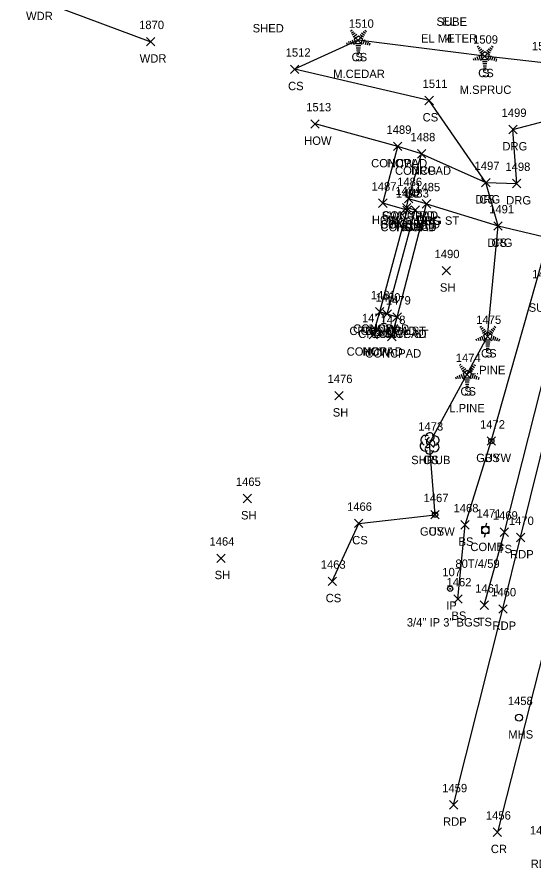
# Model space of a CAD drawing. Extents: x 1477930 to 1480780, y 774090 to 784647.
# Drawn here: x 1479170.3 to 1479293.7, y 774132.1 to 774335.2 of the extents above; entities that cross this region are included whole.
import ezdxf

# ---------------------------------------------------------------- set-up
doc = ezdxf.new("R2010")
doc.units = 0
for name, color, linetype in [('L_A', 7, 'Continuous'), ('L_C', 7, 'Continuous'), ('L_I', 7, 'Continuous'), ('L_TIC', 7, 'Continuous'), ('LAWA', 7, 'Continuous'), ('LBC', 7, 'Continuous'), ('LELB', 7, 'Continuous'), ('LS', 7, 'Continuous'), ('LSH', 7, 'Continuous'), ('LTC', 7, 'Continuous'), ('M_A', 7, 'Continuous'), ('M_C', 7, 'Continuous'), ('M_I', 7, 'Continuous'), ('MPIR', 7, 'Continuous'), ('P_A', 7, 'Continuous'), ('P_I', 7, 'Continuous'), ('P_TIC', 7, 'Continuous'), ('PET', 7, 'Continuous'), ('PRC', 7, 'Continuous'), ('R_A', 7, 'Continuous'), ('R_I', 7, 'Continuous'), ('R_TIC', 7, 'Continuous'), ('RDG', 7, 'Continuous'), ('RSW', 7, 'Continuous'), ('U_A', 7, 'Continuous'), ('U_C', 7, 'Continuous'), ('U_I', 7, 'Continuous'), ('UP', 7, 'Continuous'), ('UPGW', 7, 'Continuous'), ('USMH', 7, 'Continuous')]:
    doc.layers.add(name, color=color, linetype=linetype)

msp = doc.modelspace()

# ---------------------------------------------------------------- linework, layer by layer
at = {"layer": 'L_TIC'}
for points in [[(1479201.22, 774328.33), (1479203.22, 774330.33)], [(1479203.22, 774328.33), (1479201.22, 774330.33)], [(1479250.69, 774328.65), (1479252.69, 774330.65)], [(1479252.69, 774328.65), (1479250.69, 774330.65)], [(1479280.89, 774324.86), (1479282.89, 774326.86)], [(1479282.89, 774324.86), (1479280.89, 774326.86)], [(1479235.54, 774321.75), (1479237.54, 774323.75)], [(1479237.54, 774321.75), (1479235.54, 774323.75)], [(1479235.54, 774321.75), (1479237.54, 774323.75)], [(1479237.54, 774321.75), (1479235.54, 774323.75)], [(1479267.64, 774314.29), (1479269.64, 774316.29)], [(1479269.64, 774314.29), (1479267.64, 774316.29)], [(1479240.43, 774308.7), (1479242.43, 774310.7)], [(1479242.43, 774308.7), (1479240.43, 774310.7)], [(1479260.16, 774303.33), (1479262.16, 774305.33)], [(1479262.16, 774303.33), (1479260.16, 774305.33)], [(1479260.16, 774303.33), (1479262.16, 774305.33)], [(1479262.16, 774303.33), (1479260.16, 774305.33)], [(1479265.85, 774301.56), (1479267.85, 774303.56)], [(1479267.85, 774301.56), (1479265.85, 774303.56)], [(1479281.17, 774294.71), (1479283.17, 774296.71)], [(1479283.17, 774294.71), (1479281.17, 774296.71)], [(1479256.59, 774289.79), (1479258.59, 774291.79)], [(1479258.59, 774289.79), (1479256.59, 774291.79)], [(1479262.75, 774290.86), (1479264.75, 774292.86)], [(1479264.75, 774290.86), (1479262.75, 774292.86)], [(1479262.26, 774288.74), (1479264.26, 774290.74)], [(1479264.26, 774288.74), (1479262.26, 774290.74)], [(1479262.38, 774288.09), (1479264.38, 774290.09)], [(1479264.38, 774288.09), (1479262.38, 774290.09)], [(1479262.38, 774288.09), (1479264.38, 774290.09)], [(1479264.38, 774288.09), (1479262.38, 774290.09)], [(1479284.08, 774284.35), (1479286.08, 774286.35)], [(1479286.08, 774284.35), (1479284.08, 774286.35)], [(1479271.72, 774273.67), (1479273.72, 774275.67)], [(1479273.72, 774273.67), (1479271.72, 774275.67)], [(1479255.85, 774263.86), (1479257.85, 774265.86)], [(1479257.85, 774263.86), (1479255.85, 774265.86)], [(1479255.85, 774263.86), (1479257.85, 774265.86)], [(1479257.85, 774263.86), (1479255.85, 774265.86)], [(1479257.62, 774263.31), (1479259.62, 774265.31)], [(1479259.62, 774263.31), (1479257.62, 774265.31)], [(1479260.01, 774262.6), (1479262.01, 774264.6)], [(1479262.01, 774262.6), (1479260.01, 774264.6)], [(1479254.31, 774258.39), (1479256.31, 774260.39)], [(1479256.31, 774258.39), (1479254.31, 774260.39)], [(1479254.31, 774258.39), (1479256.31, 774260.39)], [(1479256.31, 774258.39), (1479254.31, 774260.39)], [(1479258.74, 774257.95), (1479260.74, 774259.95)], [(1479260.74, 774257.95), (1479258.74, 774259.95)], [(1479281.57, 774257.97), (1479283.57, 774259.97)], [(1479283.57, 774257.97), (1479281.57, 774259.97)], [(1479276.67, 774248.87), (1479278.67, 774250.87)], [(1479278.67, 774248.87), (1479276.67, 774250.87)], [(1479246.15, 774243.86), (1479248.15, 774245.86)], [(1479248.15, 774243.86), (1479246.15, 774245.86)], [(1479267.73, 774232.51), (1479269.73, 774234.51)], [(1479269.73, 774232.51), (1479267.73, 774234.51)], [(1479282.47, 774233), (1479284.47, 774235)], [(1479284.47, 774233), (1479282.47, 774235)], [(1479224.26, 774219.31), (1479226.26, 774221.31)], [(1479226.26, 774219.31), (1479224.26, 774221.31)], [(1479269.05, 774215.44), (1479271.05, 774217.44)], [(1479271.05, 774215.44), (1479269.05, 774217.44)], [(1479250.84, 774213.37), (1479252.84, 774215.37)], [(1479252.84, 774213.37), (1479250.84, 774215.37)], [(1479276.2, 774213.02), (1479278.2, 774215.02)], [(1479278.2, 774213.02), (1479276.2, 774215.02)], [(1479276.2, 774213.02), (1479278.2, 774215.02)], [(1479278.2, 774213.02), (1479276.2, 774215.02)], [(1479285.59, 774211.27), (1479287.59, 774213.27)], [(1479287.59, 774211.27), (1479285.59, 774213.27)], [(1479285.59, 774211.27), (1479287.59, 774213.27)], [(1479287.59, 774211.27), (1479285.59, 774213.27)], [(1479217.97, 774205.06), (1479219.97, 774207.06)], [(1479219.97, 774205.06), (1479217.97, 774207.06)], [(1479244.52, 774199.55), (1479246.52, 774201.55)], [(1479246.52, 774199.55), (1479244.52, 774201.55)], [(1479274.52, 774195.34), (1479276.52, 774197.34)], [(1479276.52, 774195.34), (1479274.52, 774197.34)], [(1479280.8, 774193.85), (1479282.8, 774195.85)], [(1479282.8, 774193.85), (1479280.8, 774195.85)]]:
    msp.add_lwpolyline(points, dxfattribs=at)
at = {"layer": 'LAWA'}
msp.add_lwpolyline([(1479132.45, 774321.38), (1479148.05, 774348), (1479175.1, 774339.47), (1479202.22, 774329.33)], dxfattribs=at)
at = {"layer": 'LBC'}
msp.add_lwpolyline([(1479255.31, 774259.39), (1479256.85, 774264.86), (1479263.38, 774289.09), (1479257.59, 774290.79), (1479261.16, 774304.33), (1479241.43, 774309.7)], dxfattribs=at)
at = {"layer": 'LELB'}
for points in [[(1479286.59, 774212.27), (1479303.75, 774279.72), (1479306.97, 774294.46), (1479314.06, 774320.63), (1479317.48, 774329.95), (1479319.72, 774342.37), (1479300.83, 774349.59), (1479294.56, 774350.02), (1479293.95, 774358.81)], [(1479314.06, 774320.63), (1479295.94, 774324.28), (1479281.89, 774325.86), (1479251.69, 774329.65), (1479236.54, 774322.75)], [(1479245.52, 774200.55), (1479251.84, 774214.37), (1479270.05, 774216.44), (1479268.73, 774233.51), (1479277.67, 774249.87), (1479282.57, 774258.97), (1479285.08, 774285.35), (1479282.17, 774295.71), (1479268.64, 774315.29), (1479236.54, 774322.75)], [(1479277.2, 774214.02), (1479283.47, 774234), (1479297.19, 774282.52), (1479300.07, 774295.97), (1479304.88, 774316.5), (1479296.39, 774315.47)], [(1479275.52, 774196.34), (1479277.2, 774214.02)], [(1479281.8, 774194.85), (1479286.59, 774212.27)]]:
    msp.add_lwpolyline(points, dxfattribs=at)
at = {"layer": 'LS'}
for points in [[(1479263.38, 774289.09), (1479263.26, 774289.74), (1479263.75, 774291.86), (1479266.85, 774302.56), (1479261.16, 774304.33)], [(1479255.31, 774259.39), (1479259.74, 774258.95), (1479261.01, 774263.6), (1479258.62, 774264.31), (1479256.85, 774264.86)]]:
    msp.add_lwpolyline(points, dxfattribs=at)
at = {"layer": 'LSH'}
msp.add_line((1479268.73, 774233.51), (1479268.73, 774233.51), dxfattribs=at)
msp.add_line((1479268.73, 774233.51), (1479268.73, 774233.51), dxfattribs=at)
msp.add_arc((1479268.78, 774234.95), 1.05, 335.5272, 180.9563, dxfattribs=at)
for centre, major_axis, ratio, start_param, end_param in [((1479267.94, 774234.18), (1.21, -0.51), 0.895232, 1.570796, 4.712389), ((1479268.53, 774233.97), (-0.208, -0.792), 0.645439, 3.141593, 6.283185), ((1479269.23, 774233.35), (-0.5, 0.667), 0.989748, 3.141593, 6.283185), ((1479269.78, 774234.1), (-1.14, -0.48), 0.949671, 1.570796, 4.712389), ((1479267.65, 774232.8), (0.58, -1.04), 0.959034, 3.141593, 6.283185), ((1479268.73, 774232.01), (0.26, 1.06), 0.942809, 1.570796, 4.712389), ((1479268.28, 774232.76), (-0.625, -0.083), 0.423636, 0, 3.141593), ((1479269.73, 774232.68), (-1.09, 0.79), 0.841452, 1.570796, 4.712389)]:
    msp.add_ellipse(centre, major_axis=major_axis, ratio=ratio, start_param=start_param, end_param=end_param, dxfattribs=at)
at = {"layer": 'LTC'}
for p, q in [((1479249.88, 774331.86), (1479250.24, 774332.12)), ((1479250.09, 774331.39), (1479250.62, 774331.78)), ((1479252.91, 774331.75), (1479253.46, 774331.35)), ((1479253.28, 774332.1), (1479253.7, 774331.79)), ((1479249.83, 774329.57), (1479250.1, 774328.73)), ((1479250.28, 774329.79), (1479250.61, 774328.77)), ((1479250.3, 774330.93), (1479251.01, 774331.44)), ((1479250.51, 774330.46), (1479251.39, 774331.1)), ((1479250.74, 774330.01), (1479251.75, 774330.74)), ((1479250.74, 774330.01), (1479251.12, 774328.81)), ((1479251.75, 774330.74), (1479252.75, 774330.02)), ((1479252.17, 774331.05), (1479252.98, 774330.46)), ((1479252.75, 774330.02), (1479252.35, 774328.81)), ((1479252.54, 774331.4), (1479253.22, 774330.91)), ((1479253.18, 774329.74), (1479252.85, 774328.7)), ((1479253.63, 774329.49), (1479253.34, 774328.61)), ((1479248.92, 774329.14), (1479249.07, 774328.67)), ((1479249.37, 774329.35), (1479249.58, 774328.7)), ((1479252.35, 774328.81), (1479251.12, 774328.81)), ((1479252.32, 774328.31), (1479251.17, 774328.31)), ((1479252.23, 774327.81), (1479251.24, 774327.81)), ((1479254.07, 774329.24), (1479253.84, 774328.51)), ((1479254.52, 774328.99), (1479254.33, 774328.42)), ((1479280.09, 774328.07), (1479280.44, 774328.33)), ((1479280.3, 774327.6), (1479280.83, 774327.99)), ((1479280.51, 774327.14), (1479281.21, 774327.65)), ((1479282.75, 774327.61), (1479283.43, 774327.12)), ((1479283.12, 774327.96), (1479283.67, 774327.56)), ((1479283.49, 774328.31), (1479283.91, 774328.01)), ((1479252.15, 774327.31), (1479251.32, 774327.31)), ((1479252.07, 774326.81), (1479251.39, 774326.81)), ((1479279.58, 774325.57), (1479279.79, 774324.91)), ((1479280.03, 774325.78), (1479280.3, 774324.95)), ((1479280.49, 774326), (1479280.82, 774324.98)), ((1479280.72, 774326.67), (1479281.6, 774327.31)), ((1479280.94, 774326.22), (1479281.96, 774326.95)), ((1479280.94, 774326.22), (1479281.33, 774325.02)), ((1479281.96, 774326.95), (1479282.95, 774326.23)), ((1479282.38, 774327.27), (1479283.18, 774326.68)), ((1479282.95, 774326.23), (1479282.56, 774325.02)), ((1479283.39, 774325.96), (1479283.05, 774324.92)), ((1479283.83, 774325.71), (1479283.55, 774324.82)), ((1479284.28, 774325.46), (1479284.04, 774324.73)), ((1479279.12, 774325.35), (1479279.27, 774324.88)), ((1479282.56, 774325.02), (1479281.33, 774325.02)), ((1479282.52, 774324.52), (1479281.38, 774324.52)), ((1479282.44, 774324.02), (1479281.45, 774324.02)), ((1479282.36, 774323.52), (1479281.52, 774323.52)), ((1479284.72, 774325.21), (1479284.54, 774324.63)), ((1479282.27, 774323.02), (1479281.6, 774323.02)), ((1479280.77, 774261.17), (1479281.12, 774261.43)), ((1479280.98, 774260.71), (1479281.51, 774261.09)), ((1479281.19, 774260.24), (1479281.89, 774260.75)), ((1479283.43, 774260.72), (1479284.1, 774260.22)), ((1479283.8, 774261.07), (1479284.35, 774260.67)), ((1479284.17, 774261.41), (1479284.59, 774261.11)), ((1479279.8, 774258.45), (1479279.95, 774257.99)), ((1479280.26, 774258.67), (1479280.47, 774258.02)), ((1479280.71, 774258.89), (1479280.98, 774258.05)), ((1479281.17, 774259.1), (1479281.5, 774258.08)), ((1479281.4, 774259.78), (1479282.28, 774260.42)), ((1479281.62, 774259.32), (1479282.63, 774260.06)), ((1479281.62, 774259.32), (1479282.01, 774258.13)), ((1479282.63, 774260.06), (1479283.63, 774259.33)), ((1479283.05, 774260.37), (1479283.86, 774259.78)), ((1479283.63, 774259.33), (1479283.24, 774258.13)), ((1479284.07, 774259.06), (1479283.73, 774258.02)), ((1479284.51, 774258.81), (1479284.23, 774257.93)), ((1479284.96, 774258.56), (1479284.72, 774257.83)), ((1479283.24, 774258.13), (1479282.01, 774258.13)), ((1479283.2, 774257.63), (1479282.06, 774257.63)), ((1479283.12, 774257.13), (1479282.13, 774257.13)), ((1479283.03, 774256.63), (1479282.2, 774256.63)), ((1479285.4, 774258.31), (1479285.22, 774257.74)), ((1479282.95, 774256.13), (1479282.28, 774256.13)), ((1479275.86, 774252.08), (1479276.22, 774252.34)), ((1479279.26, 774252.32), (1479279.68, 774252.02)), ((1479276.07, 774251.62), (1479276.6, 774252)), ((1479276.28, 774251.15), (1479276.99, 774251.66)), ((1479276.49, 774250.68), (1479277.37, 774251.32)), ((1479276.72, 774250.23), (1479277.73, 774250.96)), ((1479277.73, 774250.96), (1479278.73, 774250.24)), ((1479278.15, 774251.28), (1479278.96, 774250.69)), ((1479278.52, 774251.63), (1479279.2, 774251.13)), ((1479278.89, 774251.97), (1479279.44, 774251.57)), ((1479274.9, 774249.36), (1479275.05, 774248.89)), ((1479275.35, 774249.58), (1479275.56, 774248.93)), ((1479275.81, 774249.79), (1479276.08, 774248.96)), ((1479276.26, 774250.01), (1479276.59, 774248.99)), ((1479276.72, 774250.23), (1479277.1, 774249.04)), ((1479278.33, 774249.04), (1479277.1, 774249.04)), ((1479278.3, 774248.54), (1479277.15, 774248.54)), ((1479278.73, 774250.24), (1479278.33, 774249.04)), ((1479279.16, 774249.97), (1479278.82, 774248.93)), ((1479279.61, 774249.72), (1479279.32, 774248.83)), ((1479280.05, 774249.47), (1479279.81, 774248.74)), ((1479280.5, 774249.22), (1479280.31, 774248.64)), ((1479278.21, 774248.04), (1479277.22, 774248.04)), ((1479278.13, 774247.54), (1479277.3, 774247.54)), ((1479278.04, 774247.04), (1479277.37, 774247.04))]:
    msp.add_line(p, q, dxfattribs=at)
at = {"layer": 'MPIR'}
for radius in [0.625, 0.0833]:
    msp.add_circle((1479273.66, 774198.76), radius, dxfattribs=at)
at = {"layer": 'P_TIC'}
for points in [[(1479289.45, 774210), (1479291.45, 774212)], [(1479291.45, 774210), (1479289.45, 774212)], [(1479289.45, 774210), (1479291.45, 774212)], [(1479291.45, 774210), (1479289.45, 774212)], [(1479285.26, 774192.96), (1479287.26, 774194.96)], [(1479287.26, 774192.96), (1479285.26, 774194.96)], [(1479273.46, 774146.2), (1479275.46, 774148.2)], [(1479275.46, 774146.2), (1479273.46, 774148.2)], [(1479283.93, 774139.68), (1479285.93, 774141.68)], [(1479285.93, 774139.68), (1479283.93, 774141.68)]]:
    msp.add_lwpolyline(points, dxfattribs=at)
at = {"layer": 'PET'}
for points in [[(1479290.45, 774211), (1479306.91, 774277.39), (1479311.78, 774295.77), (1479318.73, 774320.25), (1479320.95, 774328.78), (1479324.18, 774341.9), (1479331.38, 774365.72), (1479345.79, 774423.22), (1479362.09, 774490.12), (1479368.03, 774516.32), (1479374.9, 774550.83), (1479383.52, 774593.51), (1479391.98, 774640.39), (1479380.39, 774660.29), (1479367.57, 774658.29), (1479344.84, 774648.04), (1479309.03, 774631.85), (1479275.88, 774616.72), (1479247.66, 774604.4), (1479226.65, 774595.78), (1479182.4, 774576.78), (1479137.48, 774556.65)], [(1479274.46, 774147.2), (1479286.26, 774193.96), (1479290.45, 774211)]]:
    msp.add_lwpolyline(points, dxfattribs=at)
at = {"layer": 'PRC'}
msp.add_lwpolyline([(1479418.32, 774694.97), (1479413.6, 774667.54), (1479403.41, 774616.88), (1479393.18, 774569.31), (1479382.15, 774520.62), (1479370.95, 774473.44), (1479362, 774437.8), (1479350.26, 774392.93), (1479347.88, 774382.5), (1479334.29, 774330.6), (1479333.84, 774328.63), (1479325.02, 774295.54), (1479313.51, 774250.57), (1479296.99, 774187.82), (1479284.93, 774140.68)], dxfattribs=at)
at = {"layer": 'R_TIC'}
for points in [[(1479287.63, 774307.37), (1479289.63, 774309.37)], [(1479289.63, 774307.37), (1479287.63, 774309.37)], [(1479265.85, 774301.56), (1479267.85, 774303.56)], [(1479267.85, 774301.56), (1479265.85, 774303.56)], [(1479281.17, 774294.71), (1479283.17, 774296.71)], [(1479283.17, 774294.71), (1479281.17, 774296.71)], [(1479288.53, 774294.48), (1479290.53, 774296.48)], [(1479290.53, 774294.48), (1479288.53, 774296.48)], [(1479262.75, 774290.86), (1479264.75, 774292.86)], [(1479264.75, 774290.86), (1479262.75, 774292.86)], [(1479267.01, 774289.63), (1479269.01, 774291.63)], [(1479269.01, 774289.63), (1479267.01, 774291.63)], [(1479267.01, 774289.63), (1479269.01, 774291.63)], [(1479269.01, 774289.63), (1479267.01, 774291.63)], [(1479262.26, 774288.74), (1479264.26, 774290.74)], [(1479264.26, 774288.74), (1479262.26, 774290.74)], [(1479264.32, 774288.15), (1479266.32, 774290.15)], [(1479266.32, 774288.15), (1479264.32, 774290.15)], [(1479284.08, 774284.35), (1479286.08, 774286.35)], [(1479286.08, 774284.35), (1479284.08, 774286.35)], [(1479257.62, 774263.31), (1479259.62, 774265.31)], [(1479259.62, 774263.31), (1479257.62, 774265.31)], [(1479260.01, 774262.6), (1479262.01, 774264.6)], [(1479262.01, 774262.6), (1479260.01, 774264.6)]]:
    msp.add_lwpolyline(points, dxfattribs=at)
at = {"layer": 'RDG'}
for points in [[(1479266.85, 774302.56), (1479282.17, 774295.71), (1479289.53, 774295.48), (1479288.63, 774308.37), (1479296.45, 774310.4), (1479300.07, 774295.97), (1479306.97, 774294.46), (1479311.78, 774295.77)], [(1479268.01, 774290.63), (1479285.08, 774285.35), (1479297.19, 774282.52), (1479303.75, 774279.72), (1479306.91, 774277.39)]]:
    msp.add_lwpolyline(points, dxfattribs=at)
at = {"layer": 'RSW'}
for points in [[(1479261.01, 774263.6), (1479268.01, 774290.63), (1479263.75, 774291.86)], [(1479258.62, 774264.31), (1479265.32, 774289.15), (1479263.26, 774289.74)]]:
    msp.add_lwpolyline(points, dxfattribs=at)
at = {"layer": 'UP'}
for p, q in [((1479282.33, 774214.43), (1479282.08, 774213.59)), ((1479281.25, 774211.93), (1479281.25, 774213.59)), ((1479281.25, 774213.59), (1479282.91, 774213.59)), ((1479282.91, 774211.93), (1479281.25, 774211.93)), ((1479281.83, 774211.09), (1479282.08, 774211.93)), ((1479282.08, 774212.76), (1479282.08, 774212.76)), ((1479282.91, 774213.59), (1479282.91, 774211.93))]:
    msp.add_line(p, q, dxfattribs=at)
msp.add_circle((1479282.08, 774212.76), 0.833, dxfattribs=at)
at = {"layer": 'UPGW'}
for centre, radius in [((1479283.47, 774234), 0.625), ((1479283.47, 774234), 0.0833), ((1479270.05, 774216.44), 0.625), ((1479270.05, 774216.44), 0.0833)]:
    msp.add_circle(centre, radius, dxfattribs=at)
at = {"layer": 'USMH'}
for p, q in [((1479290.1, 774168.01), (1479290.1, 774168.01)), ((1479290.94, 774168.01), (1479290.94, 774168.01))]:
    msp.add_line(p, q, dxfattribs=at)
msp.add_circle((1479290.1, 774168.01), 0.833, dxfattribs=at)

# ---------------------------------------------------------------- texts
at = {"layer": 'L_A'}
for s, p in [('WDR', (1479172.46, 774334.47)), ('SHED', (1479226.53, 774331.54)), ('SHED', (1479226.53, 774331.54)), ('WDR', (1479199.58, 774324.33)), ('CS', (1479250.13, 774324.65)), ('S', (1479251.07, 774324.65)), ('CS', (1479280.34, 774320.86)), ('S', (1479281.28, 774320.86)), ('CS', (1479234.98, 774317.75)), ('CS', (1479234.98, 774317.75)), ('CS', (1479267.08, 774310.29)), ('HOW', (1479238.82, 774304.7)), ('CONCPAD', (1479254.8, 774299.33)), ('HOW', (1479258.54, 774299.33)), ('CONCPAD', (1479260.5, 774297.56)), ('CS', (1479280.61, 774290.71)), ('CONCPAD', (1479257.4, 774286.86)), ('HOW', (1479254.98, 774285.79)), ('CONCPAD', (1479256.91, 774284.74)), ('CONCPAD', (1479257.03, 774284.09)), ('HOW', (1479260.77, 774284.09)), ('CS', (1479283.52, 774280.35)), ('SH', (1479271.21, 774269.67)), ('CONCPAD', (1479250.5, 774259.86)), ('CONCPAD', (1479252.27, 774259.31)), ('HOW', (1479254.24, 774259.86)), ('CONCPAD', (1479254.65, 774258.6)), ('CONCPAD', (1479248.96, 774254.39)), ('HOW', (1479252.7, 774254.39)), ('CONCPAD', (1479253.38, 774253.95)), ('CS', (1479281.02, 774253.97)), ('S', (1479281.96, 774253.97)), ('CS', (1479276.11, 774244.87)), ('S', (1479277.05, 774244.87)), ('SH', (1479245.64, 774239.86)), ('SHRUB', (1479264.36, 774228.51)), ('CS', (1479267.18, 774228.51)), ('BS', (1479281.92, 774229)), ('SH', (1479223.75, 774215.31)), ('CS', (1479268.49, 774211.44)), ('CS', (1479250.28, 774209.37)), ('BS', (1479275.65, 774209.02)), ('BS', (1479275.65, 774209.02)), ('TS', (1479285, 774207.27)), ('TS', (1479285, 774207.27)), ('SH', (1479217.46, 774201.06)), ('CS', (1479243.96, 774195.55)), ('BS', (1479273.96, 774191.34)), ('TS', (1479280.21, 774189.85))]:
    msp.add_text(s, height=2, dxfattribs=at).set_placement(p)
at = {"layer": 'L_C'}
for s, p in [('M.CEDAR', (1479245.74, 774320.65)), ('M.SPRUC', (1479275.92, 774316.86)), ('L.PINE', (1479278.35, 774249.97)), ('L.PINE', (1479273.45, 774240.87))]:
    msp.add_text(s, height=2, dxfattribs=at).set_placement(p)
at = {"layer": 'L_I'}
for s, p in [('1870', (1479199.44, 774332.33)), ('1510', (1479249.48, 774332.65)), ('1510', (1479249.48, 774332.65)), ('1509', (1479279.12, 774328.86)), ('1509', (1479279.12, 774328.86)), ('1512', (1479234.41, 774325.75)), ('1512', (1479234.41, 774325.75)), ('1508', (1479293.17, 774327.28)), ('1511', (1479267.08, 774318.29)), ('1513', (1479239.31, 774312.7)), ('1489', (1479258.46, 774307.33)), ('1489', (1479258.46, 774307.33)), ('1488', (1479264.16, 774305.56)), ('1497', (1479279.48, 774298.71)), ('1487', (1479254.9, 774293.79)), ('1486', (1479261.01, 774294.86)), ('1484', (1479260.57, 774292.74)), ('1482', (1479260.69, 774292.09)), ('1482', (1479260.69, 774292.09)), ('1491', (1479282.95, 774288.35)), ('1490', (1479269.94, 774277.67)), ('1481', (1479254.73, 774267.86)), ('1481', (1479254.73, 774267.86)), ('1480', (1479255.84, 774267.31)), ('1479', (1479258.31, 774266.6)), ('1477', (1479252.62, 774262.39)), ('1477', (1479252.62, 774262.39)), ('1478', (1479257.04, 774261.95)), ('1475', (1479279.88, 774261.97)), ('1475', (1479279.88, 774261.97)), ('1474', (1479274.98, 774252.87)), ('1474', (1479274.98, 774252.87)), ('1476', (1479244.4, 774247.86)), ('1473', (1479266.04, 774236.51)), ('1473', (1479266.04, 774236.51)), ('1472', (1479280.78, 774237)), ('1465', (1479222.52, 774223.31)), ('1467', (1479267.31, 774219.44)), ('1466', (1479249.05, 774217.37)), ('1468', (1479274.46, 774217.02)), ('1468', (1479274.46, 774217.02)), ('1469', (1479283.84, 774215.27)), ('1469', (1479283.84, 774215.27)), ('1464', (1479216.23, 774209.06)), ('1463', (1479242.78, 774203.55)), ('1462', (1479272.78, 774199.34)), ('1461', (1479279.63, 774197.85))]:
    msp.add_text(s, height=2, dxfattribs=at).set_placement(p)
at = {"layer": 'LTC'}
for p in [(1479251.63, 774329.75), (1479281.84, 774325.97), (1479282.52, 774259.07), (1479277.61, 774249.98)]:
    msp.add_text('.', height=1.04, rotation=270, dxfattribs=at).set_placement(p)
at = {"layer": 'M_A'}
msp.add_text('IP', height=2, dxfattribs=at).set_placement((1479272.71, 774193.76))
at = {"layer": 'M_C'}
msp.add_text('3/4" IP 3" BGS', height=2, dxfattribs=at).set_placement((1479263.31, 774189.76))
at = {"layer": 'M_I'}
msp.add_text('107', height=2, dxfattribs=at).set_placement((1479271.79, 774201.76))
at = {"layer": 'P_A'}
for s, p in [('RDP', (1479287.94, 774206)), ('RDP', (1479287.94, 774206)), ('RDP', (1479283.75, 774188.96)), ('RDP', (1479271.95, 774142.2)), ('CR', (1479283.36, 774135.68)), ('RDP', (1479292.87, 774132.13))]:
    msp.add_text(s, height=2, dxfattribs=at).set_placement(p)
at = {"layer": 'P_I'}
for s, p in [('1470', (1479287.67, 774214)), ('1470', (1479287.67, 774214)), ('1460', (1479283.44, 774196.96)), ('1459', (1479271.76, 774150.2)), ('1456', (1479282.18, 774143.68)), ('1457', (1479292.69, 774140.13))]:
    msp.add_text(s, height=2, dxfattribs=at).set_placement(p)
at = {"layer": 'R_A'}
for s, p in [('DRG', (1479286.12, 774303.37)), ('DRG', (1479264.34, 774297.56)), ('DRG', (1479279.66, 774290.71)), ('DRG', (1479287.02, 774290.48)), ('SWC CPD', (1479257.34, 774286.86)), ('SWC DRG ST', (1479258.73, 774285.63)), ('DRG', (1479265.5, 774285.63)), ('SWC1 CPD', (1479257.13, 774284.74)), ('SWC1', (1479262.36, 774284.15)), ('DRG', (1479282.57, 774280.35)), ('CPD SWC1 ST', (1479249.62, 774259.31)), ('CPD SWC ST', (1479251.72, 774258.6))]:
    msp.add_text(s, height=2, dxfattribs=at).set_placement(p)
at = {"layer": 'R_I'}
for s, p in [('1499', (1479285.93, 774311.37)), ('1488', (1479264.16, 774305.56)), ('1497', (1479279.48, 774298.71)), ('1498', (1479286.84, 774298.48)), ('1486', (1479261.01, 774294.86)), ('1485', (1479265.32, 774293.63)), ('1485', (1479265.32, 774293.63)), ('1484', (1479260.57, 774292.74)), ('1483', (1479262.62, 774292.15)), ('1491', (1479282.95, 774288.35)), ('1480', (1479255.84, 774267.31)), ('1479', (1479258.31, 774266.6))]:
    msp.add_text(s, height=2, dxfattribs=at).set_placement(p)
at = {"layer": 'U_A'}
for s, p in [('SUBE', (1479270.4, 774333.11)), ('EL', (1479271.8, 774333.17)), ('SUBW', (1479292.39, 774264.87)), ('GUYW', (1479279.87, 774229)), ('GUYW', (1479266.44, 774211.44)), ('COMB', (1479278.47, 774207.76)), ('MHS', (1479287.52, 774163.01))]:
    msp.add_text(s, height=2, dxfattribs=at).set_placement(p)
at = {"layer": 'U_C'}
for s, p in [('EL METER', (1479266.71, 774329.11)), ('4', (1479272.7, 774329.17)), ('80T/4/59', (1479274.91, 774203.76))]:
    msp.add_text(s, height=2, dxfattribs=at).set_placement(p)
at = {"layer": 'U_I'}
for s, p in [('1496', (1479293.23, 774272.87)), ('1472', (1479280.78, 774237)), ('1467', (1479267.31, 774219.44)), ('1471', (1479279.95, 774215.76)), ('1458', (1479287.41, 774171.01))]:
    msp.add_text(s, height=2, dxfattribs=at).set_placement(p)

doc.saveas('drawing.dxf')
